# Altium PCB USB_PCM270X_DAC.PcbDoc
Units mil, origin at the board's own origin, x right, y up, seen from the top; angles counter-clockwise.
Board outline 1771 x 2186.5 mil, 2 copper layers (TopLayer, BottomLayer); 75 components, 58 nets, 240 pads, 54 vias.
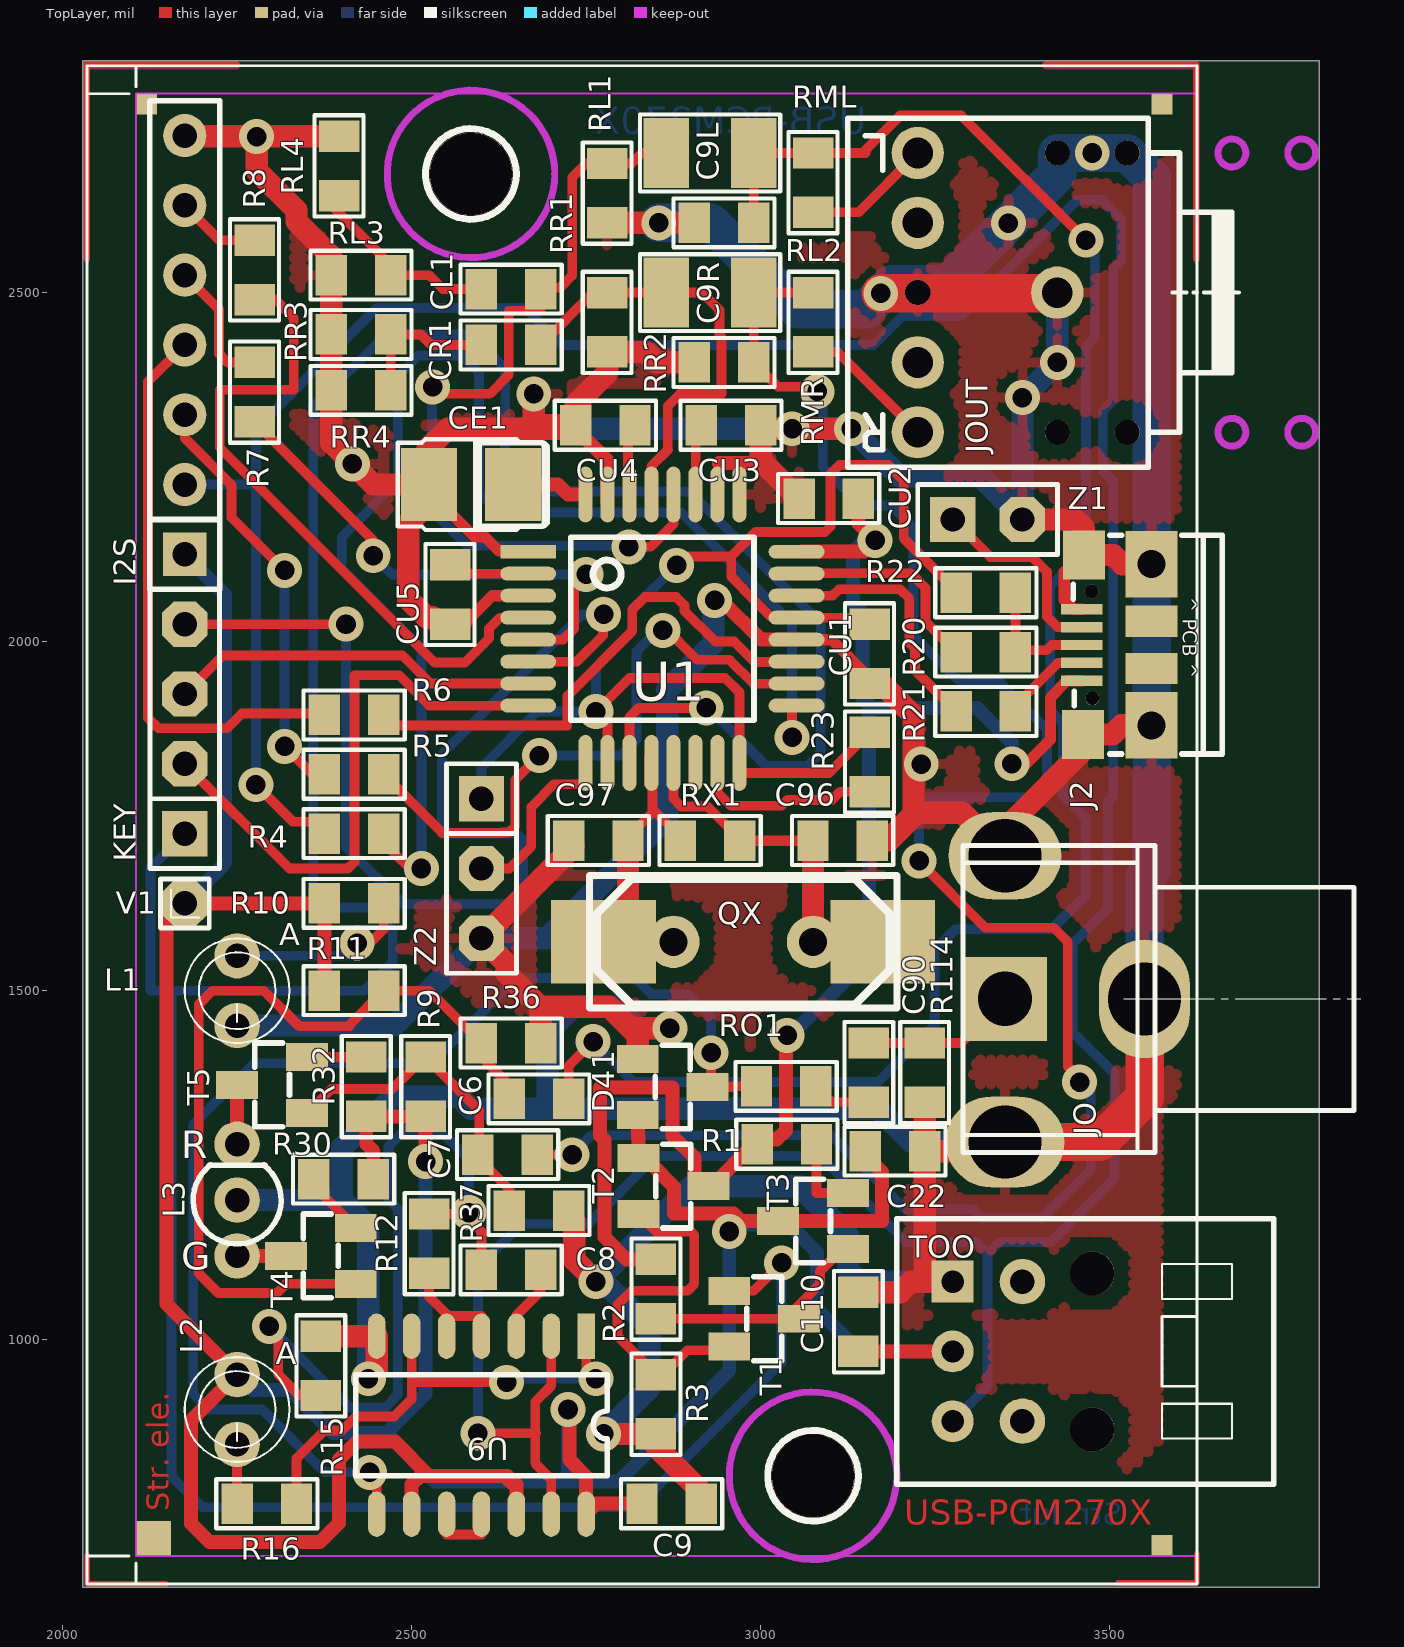
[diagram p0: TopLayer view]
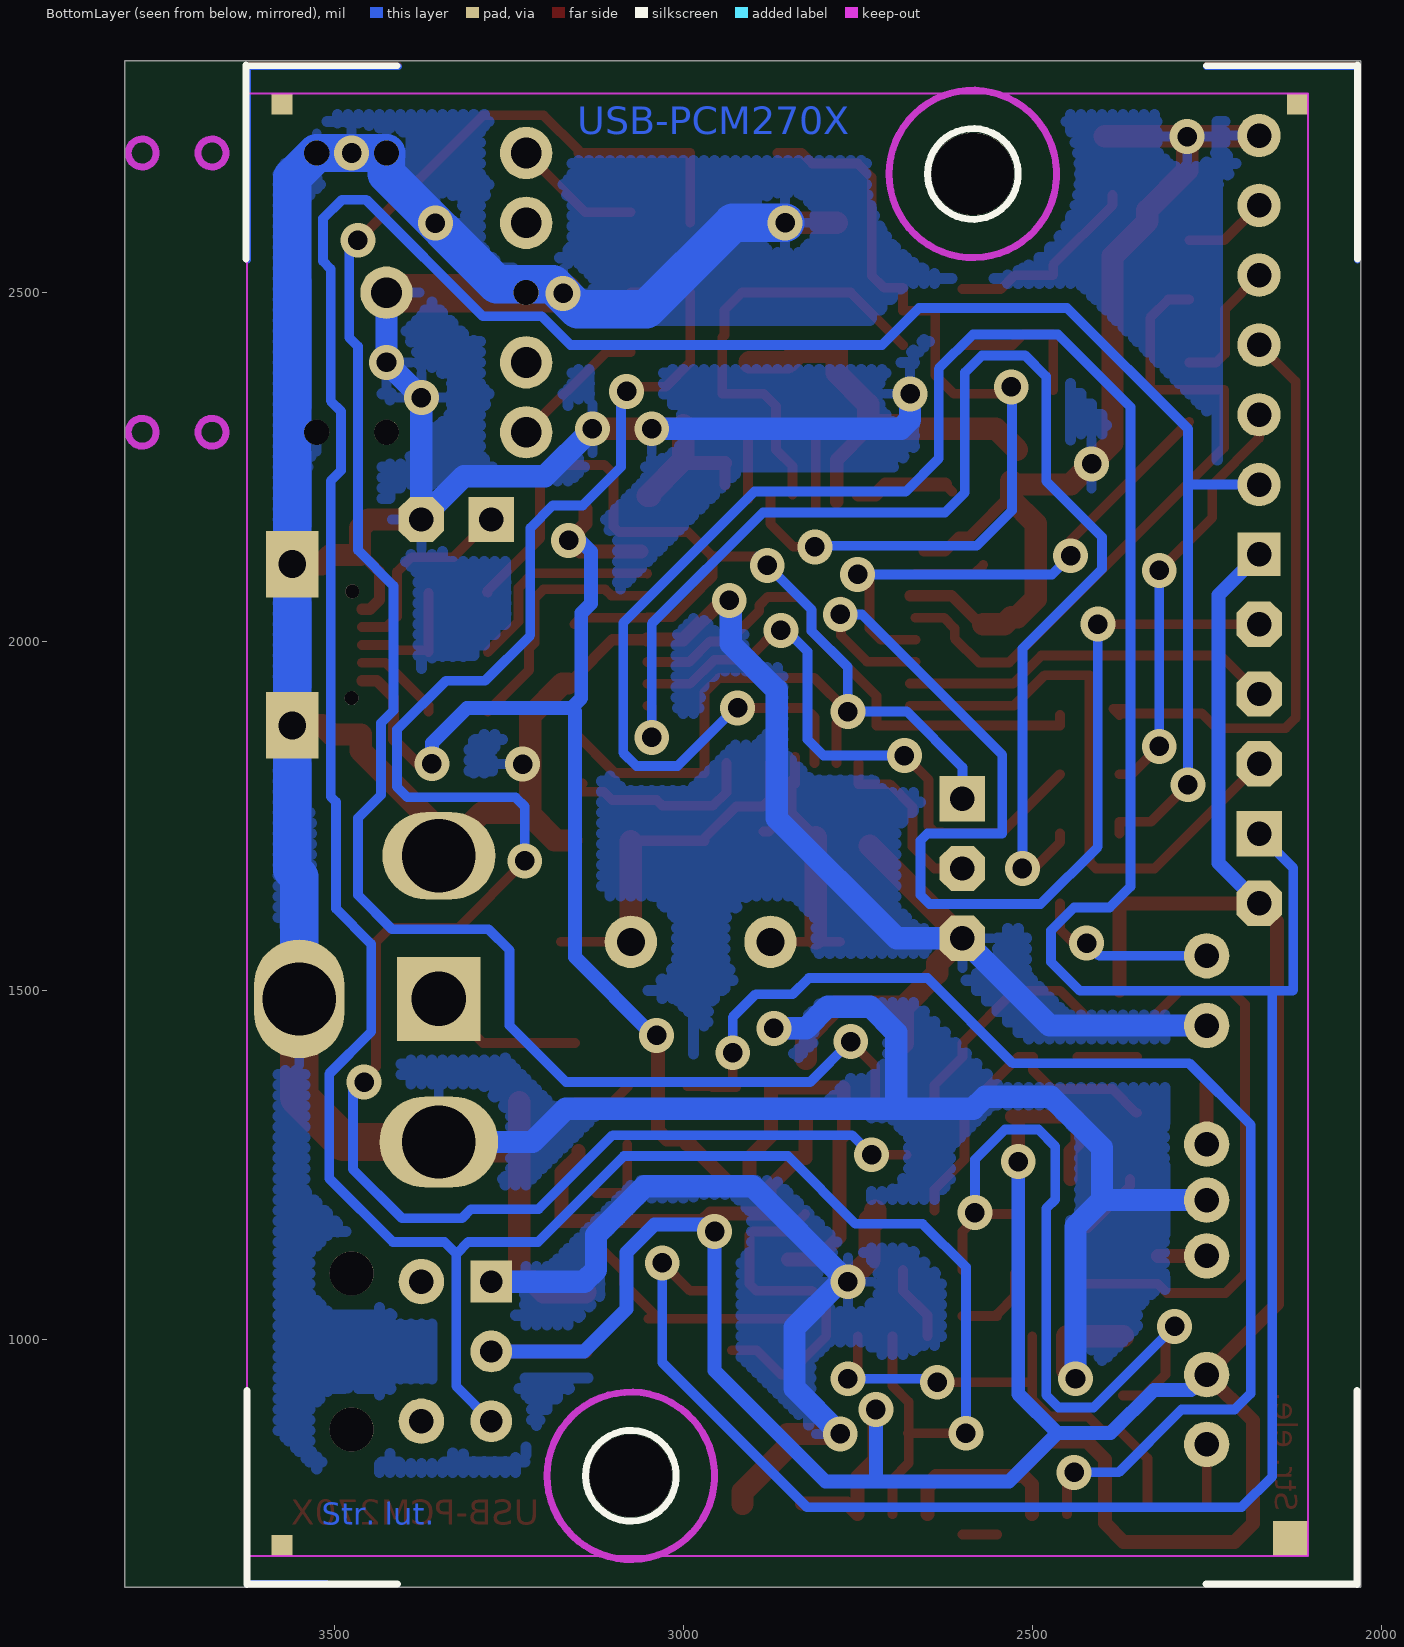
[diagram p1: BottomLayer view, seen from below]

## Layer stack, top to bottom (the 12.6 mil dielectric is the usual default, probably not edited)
TopLayer: signal copper 1.4
Dielectric: dielectric 12.6, FR-4, Dk 4.8
BottomLayer: signal copper 1.4

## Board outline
2029,645.5 3800,645.5 3800,2832 2029,2832

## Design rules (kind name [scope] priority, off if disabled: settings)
Clearance Clearance_2 [All] p1 off: gap=20
Clearance Clearance_1 [All] p2 off: gap=20
Clearance [All] p3: gap=9
ComponentClearance [All] p1: gap=-200 collisioncheckmode=3 verticalgap=10 showdistances=FALSE
FabricationTestPointUsage TestPointUsage [All] p1: valid=0 allowmultiple=FALSE
FabricationTestpoint Testpoint [All] p1: side=3 testpointundercomponent=TRUE minsize=40 maxsize=100 preferedsize=60 minholesize=20 maxholesize=40 preferedholesize=32 testpointgrid=1 allowsidetop=TRUE allowsidebottom=TRUE usegrid=TRUE gridtolerance=0.01
PlaneClearance [All] p1: clearance=10
PlaneConnect [All] p1: planeconnectstyle=Relief reliefexpansion=14 reliefentries=4 reliefconductorwidth=16 reliefairgap=10
PolygonConnect [All] p1: connectstyle=Relief reliefconductorwidth=14 reliefentries=4 polygonreliefangle="90 Angle"
RoutingCorners [All] p1: cornerstyle=45-Degree minsetback=10 maxsetback=200
RoutingPriority [All] p1: routingpriority=2
RoutingVias RoutingVias_B [InNetClass('BOLD3')] p1: holewidth=35 width=65 viastyle="Through Hole" minholewidth=28 minwidth=50 maxholewidth=63 maxwidth=100
RoutingVias [All] p2: holewidth=28 width=50 viastyle="Through Hole" minholewidth=28 minwidth=50 maxholewidth=63 maxwidth=100
SilkscreenOverComponentPads [All] p1: minsilkscreentomaskgap=10
SolderMaskExpansion [All] p1: expansion=2
Width Width_B [InNetClass('BOLD')] p1: maxlimit=100 minlimit=14 preferedwidth=32
Width Width_S [InNetClass('Srednie')] p2: maxlimit=100 minlimit=14 preferedwidth=20
Width [All] p3: maxlimit=100 minlimit=12 preferedwidth=14
20 further rules are at their usual default settings.

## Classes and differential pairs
net class Srednie: VBUS VCC
net class BOLD: GND

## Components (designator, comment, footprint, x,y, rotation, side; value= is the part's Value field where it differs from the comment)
C6 "1u0" 0805_C 2725,1345 r180 top
C7 "1u0" 0805_C 2680,1265 r180 top
C8 "100n" 0805_C 2685,1100 r180 top
C9 "100n" 0805_C 2830,765 r0 top
C9L "47uFc" 1210_C 2865,2700 r0 top
C9R "47uFc" 1210_C 2865,2500 r0 top
C22 "470n" 0805_C 3150,1270 r0 top
C90 "100n" 0805_C 3155,1340 r90 top
C96 "12p" 0805_C 3160,1715 r180 top
C97 "12p" 0805_C 2725,1715 r0 top
C110 "100n" 0805_C 3140,983.19 r90 top
CE1 "10uF" 3528_B 2635,2225 r180 top
CL1 "22n" 0805_C 2600,2505 r0 top
CR1 "22n" 0805_C 2600,2425 r0 top
CU1 "4u7" 0805_C 3156,1940 r90 top
CU2 "1u0" 0805_C 3055,2205 r0 top
CU3 "1u0" 0805_C 2915,2310 r0 top
CU4 "1u0" 0805_C 2735,2310 r0 top
CU5 "1u0" 0805_C 2555,2025 r90 top
D41 "BAT54S" SOT-23B_3D 2924,1362 r90 top
I2S "[7]" SIP7 2175,2125 r90 top
J2 "MICRO_USB_FV" MICRO_USB_FV_2 3460,1944 r180 top
JO "SPDIFOUT" CHINCH1_3D 3550,1488.19 r270 top
JOUT "JACK_OUT" JACK_NC+_3D 3425,2500 r180 top
KEY "[4]" SIP4 2175,1725 r90 top
L1 "LEDCZ" LED 2250,1550 r270 top
L2 "LEDBlue" LED 2250,950 r270 top
L3 "LED2C" LEDBD3 2250,1200 r270 top
QX "12MHz" XTAL5_3D 3075,1570 r180 top
R1 "10R" 0805_R 2995,1280 r0 top
R2 "1k5" 0805_R 2850,1115 r270 top
R3 "1k5" 0805_R 2850,865 r90 top
R4 "33R" 0805_R 2375,1725 r0 top
R5 "33R" 0805_R 2375,1810 r0 top
R6 "33R" 0805_R 2375,1895 r0 top
R7 "33R" 0805_R 2275,2400 r270 top
R8 "180R" 0805_R 2275,2575 r270 top
R9 "6k8" 0805_R 2520,1405 r270 top
R10 "470R" 0805_R 2375,1625 r0 top
R11 "6k8" 0805_R 2460,1500 r180 top
R12 "10k" 0805_R 2525,1095 r90 top
R15 "10k" 0805_R 2370,1005 r270 top
R16 "470R" 0805_R 2335,765 r180 top
R20 "22R" 0805_R 3365,1985 r180 top
R21 "22R" 0805_R 3365,1900 r180 top
R22 "1k5" 0805_R 3280,2070 r0 top
R23 "1k5" 0805_R 3156,1785 r90 top
R30 "200R" 0805_R 2360,1230 r0 top
R32 "330R" 0805_R 2435,1405 r270 top
R36 "39k" 0805_R 2685,1425 r180 top
R37 "39k" 0805_R 2725,1185 r180 top
R114 "200R" 0805_R 3235,1425 r270 top
RL1 "3k3" 0805_R 2780,2600 r90 top
RL2 "3k3" 0805_R 2905,2600 r0 top
RL3 "33R" 0805_R 2385,2525 r0 top
RL4 "33R" 0805_R 2396,2724 r270 top
RML "56R" 0805_R 3075,2615 r90 top
RMR "56R" 0805_R 3075,2415 r90 top
RO1 "120R" 0805_R 2994,1363 r0 top
RR1 "3k3" 0805_R 2780,2415 r90 top
RR2 "3k3" 0805_R 2905,2400 r0 top
RR3 "33R" 0805_R 2385,2440 r0 top
RR4 "33R" 0805_R 2385,2360 r0 top
RX1 "1M0" 0805_R 2970,1715 r180 top
T1 "BC847" SOT-23X_3D 3055,1030 r90 top
T2 "BC847" SOT-23X_3D 2925,1220 r90 top
T3 "BC857" SOT-23X_3D 3025,1170 r270 top
T4 "BC857" SOT-23X_3D 2320,1120 r270 top
T5 "BC857" SOT-23X_3D 2250,1365 r270 top
TOO "TOTX147PL" TOTX147_3D 3275,1083.19 r90 top
U1 "PCM2706" TQFP32_3D 2667,2128.79 r0 top
U9 "74LV00" SMD14_3D 2750,980 r270 top
V1 "Vcc" VIA 2175,1625 r0 top
Z1 "z" SIP2 3275,2175 r0 top
Z2 "FS" SIP3 2600,1775 r270 top

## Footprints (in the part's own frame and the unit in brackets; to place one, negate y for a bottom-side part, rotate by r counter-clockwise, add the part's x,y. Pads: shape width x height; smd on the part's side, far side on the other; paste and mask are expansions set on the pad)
0805_C [mil]
  rect 45x58 smd paste-2: 1(0,0) 2(85,0)
  silkscreen extent -30,-35 115,35
0805_R [mil]
  rect 45x58 smd paste-2: 1(0,0) 2(85,0)
  silkscreen extent -30,-35 115,35
1210_C [mil]
  rect 65x100 smd: 1(0,0) 2(125,0)
  silkscreen extent -38,-55 163,55
3528_B [mil]
  rect 80x105 smd paste-5: 1(-10,0) 2(110,0)
  silkscreen extent -60,-65 155,65
CHINCH1_3D [mil]
  rect 120x120 hole 78: 1(0,-200)
  oval 170x130 hole 105: 2(0,0)
  oval 125x162 hole 105: 3(-205,-200)
  oval 130x170 hole 105: 4(205,-200)
  silkscreen extent -220,-260 220,310
JACK_NC+_3D [mil]
  round 75 hole 44: 1(200,200) 2(200,-200) 3(0,0) 4(200,100) 5(200,-100)
  round 36 hole 36 unplated: 101(-100,200) 102(0,200) 103(200,0) 104(0,-200) 105(-100,-200)
  silkscreen extent -260,-250 300,250
LED [mil]
  round 65 hole 35: A(0,0) K(100,0)
  silkscreen extent -25,-75 125,75
LEDBD3 [mil]
  round 65 hole 35: 1(-80,0) 2(0,0) 3(80,0)
  silkscreen extent -50,-63 63,63
MICRO_USB_FV_2 [mil]
  rect 59x15 smd: 1(0,0) 2(0,-25.59) 3(0,-51.18) 4(0,-76.77) 5(0,-102.36)
  rect 75x95 hole 40: 10(-100,64) 11(-100,-167)
  rect 60x70 smd: 100(-2,77) 101(-3,-180)
  rect 75x45 smd: 101(-100,-17.5) 102(-100,-85)
  round 20 hole 20 unplated: 110(-15,25) 111(-14,-128)
  silkscreen extent -202,-209 12,105
SIP2 [mil]
  rect 65x65 hole 35: 1(0,0)
  oct 65x65 hole 35: 2(100,0)
  silkscreen extent -50,-50 150,50
SIP3 [mil]
  rect 65x65 hole 35: 1(0,0)
  oct 65x65 hole 35: 2(100,0) 3(200,0)
  silkscreen extent -50,-50 250,50
SIP4 [mil]
  rect 65x65 hole 35: 1(0,0)
  oct 65x65 hole 35: 2(100,0) 3(200,0) 4(300,0)
  silkscreen extent -50,-50 350,50
SIP7 [mil]
  rect 62x62 hole 35: 1(0,0)
  round 62 hole 35: 2(100,0) 3(200,0) 4(300,0) 5(400,0) 6(500,0) 7(600,0)
  silkscreen extent -50,-50 650,50
SMD14_3D [mil]
  rect 65x25 smd: 1(-25,0)
  oval 65x25 smd: 2(-25,-50) 3(-25,-100) 4(-25,-150) 5(-25,-200) 6(-25,-250) 7(-25,-300) 8(230,-300) 9(230,-250) 10(230,-200) 11(230,-150) 12(230,-100) 13(230,-50) 14(230,0)
  silkscreen extent 30,-330 175,30
SOT-23B_3D [mil]
  rect 40x60 smd paste-2: 1(40,100) 2(-40,100) 3(0,0)
  silkscreen extent -60,25 60,75
SOT-23X_3D [mil]
  rect 40x60 smd paste-2: B(40,100) C(0,0) E(-40,100)
  silkscreen extent -60,25 60,75
TOTX147_3D [mil]
  rect 60x60 hole 32: 1(0,0)
  round 60 hole 32: 2(-100,0) 3(-200,0)
  round 65 hole 35: 4(0,-100) 5(-200,-100)
  round 63 hole 63: 6(11.81,-200) 7(-211.81,-200)
  silkscreen extent -290,-460 90,80
TQFP32_3D [mil]
  rect 80x20 smd: 1(0,0)
  oval 80x20 smd: 2(0,-31.5) 3(0,-63) 4(0,-94.5) 5(0,-126) 6(0,-157.5) 7(0,-189) 8(0,-220.5) 17(384.5,-220.5) 18(384.5,-189) 19(384.5,-157.5) 20(384.5,-126) 21(384.5,-94.5) 22(384.5,-63) 23(384.5,-31.5) 24(384.5,0)
  oval 20x80 smd: 9(82,-302.5) 10(113.5,-302.5) 11(145,-302.5) 12(176.5,-302.5) 13(208,-302.5) 14(239.5,-302.5) 15(271,-302.5) 16(302.5,-302.5) 25(302.5,82) 26(271,82) 27(239.5,82) 28(208,82) 29(176.5,82) 30(145,82) 31(113.5,82) 32(82,82)
  silkscreen extent 61,-242 324,21
VIA [mil]
  oct 65x65 hole 35: 1(0,0)
  silkscreen extent -35,-35 35,35
XTAL5_3D [mil]
  round 75 hole 40: 1(0,0) 2(200,0)
  rect 150x120 smd: 3(-100,0) 4(300,0)
  silkscreen extent -120,-95 320,95

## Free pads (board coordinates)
  round 118 hole 118 unplated paste-5: 2(2585,2670) 2(3075,805)
  rect 30x30 all layers, no hole: 101(2120,2770) 101(3575,705) 101(3575,2770)
  rect 50x50 all layers, no hole: 102(2130,715)

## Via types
v1: diameter 50, hole 28, TopLayer to BottomLayer, tented both sides, 54 vias

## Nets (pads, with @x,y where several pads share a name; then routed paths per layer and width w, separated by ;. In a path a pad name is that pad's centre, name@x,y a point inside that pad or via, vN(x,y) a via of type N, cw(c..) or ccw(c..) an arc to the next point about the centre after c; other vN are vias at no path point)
BCLK: I2S.4 R6.1 | length 866.1
  TopLayer w14: I2S.4 2122.5,2372.5 2122.5,1890.5 2137,1876 2236,1876 2257,1897 2377,1897 2384,1904 2366,1904 R6.1
DIN: I2S.6 R8.1 | length 120.7
  TopLayer w14: I2S.6 2225,2575 R8.1
GND: C9.2 C22.2 C96.1 C97.1 C110.2 CE1.2 CU1.1 CU2.1 CU3.2 CU4.1 CU5.1 D41.1 I2S.7 J2.5 J2.10 J2.11 J2.100 J2.101@3463,2124 JO.2 JO.3 JO.4 JOUT.3 JOUT.101 JOUT.103 JOUT.104 JOUT.105 L1.K L3.2 R3.1 R15.1 R36.1 R37.1 R114.2 RL1.1 RL2.1 RL3.1 RL4.1 RR1.1 RR2.1 RR3.1 RR4.1 TOO.1 U1.1 U1.3 U1.20 U1.25 U1.26 U1.31 U9.7 Z1.2 Z2.3 | length 13405.8
  TopLayer w16: CE1.2@2525,2215 2590,2150 2605,2150 2625,2130 U1.1@2655,2130 ; CU5.1@2580,2030 2615.79,2065.79 U1.3@2675,2065.79 ; U1.26@2940,2224.79 2940,2256 ; U1.20 3101.21,2002.79 3156,1948 CU1.1 ; J2.101@3450,2115 3435,2100 3435,2060 3448.64,2046.36 J2.5
  TopLayer w20: CU4.1 2735,2305 2780,2260 U1.31@2780,2200.5 ; v1@2932,2057 2946,2057 3000.21,2002.79 U1.20 ; 2940,2256 2994.5,2256 3000,2261.5
  TopLayer w32: I2S.7 2176,2724 v1@2278,2724 ; R15.1 U9.7 2450,956 v1(2438,944) ; RL4.1 v1@2278,2724 ; CE1.2@2522,2275 2552,2305 CU4.1@2735,2305 ; CU5.1@2570,2025 2540,2025 2530,2035 2521,2035 2495,2061 2495,2169 2530,2204 2530,2230 CE1.2 2445,2225 2385,2285 RR4.1 RR3.1 RL3.1 2385,2552 2335,2602 2335,2618 2278,2675 v1@2278,2724 ; v1(2675,2355) 2675,2318 2683,2310 CU4.1 2735,2340 2780,2385 RR1.1 2835,2415 2850,2400 RR2.1 ; R37.1 R37.1@2725,1179 ; C97.1@2732.5,1707.5 Z2.3 2636,1539 2636,1525 2685,1476 R36.1 2685,1477 2783,1477 2824,1436 D41.1 2824,1446 v1(2870,1446) ; v1(2764,1083) 2733,1114 R37.1@2733,1171 ; v1(2775,865) R3.1 2850,847 2915,782 C9.2 ; RL1.1 v1(2854,2600) RL2.1 ; 3000,2260 3051.21,2208.79 CU2.1@3047,2208.79 ; 3000,2261.5 CU3.2@3000,2305 ; CU3.2 CU3.2@3000,2305 ; v1(3045,2305) CU3.2@3000,2305 ; v1@3051,2305 v1(3130,2305) ; C110.2 3200,1068.19 3215,1083.19 TOO.1 3235,1083.19 C22.2 ; CU1.1@3165,1940 3172.86,1940 3219,1893.86 3219,1750 3184,1715 C96.1 3181.86,1715 3221.86,1755 3288.19,1755 JO.3 3388.19,1693.19 3364,1717.38 3364,1746 3462,1844 J2.100 3504,1867 3517,1880 J2.10 ; R114.2 C22.2 ; JO.4 3298.19,1283.19 3285,1270 C22.2 ; Z1.2 3450.5,2175 3463,2162.5 3463,2124 3505,2124 3518,2111 J2.11 ; R37.1@2725,1179 2725,1171 R37.1@2733,1171 ; R37.1@2725,1179 R37.1@2733,1171
  TopLayer w55: v1(3172,2499) 3424,2499 JOUT.3 ; JO.4 3486.19,1283.19 3550,1347 JO.2@3550,1483.19
  BottomLayer w32: L3.2 2400,1200 ; L1.K 2475,1450 Z2.3 2694,1575 2866,1747 2866,1931 2932,1997 2932,2057 v1(2934,2059) ; v1(2438,944) 2438,1162 2400,1200 ; v1(2675,2355) 2675,2318 2688,2305 v1(3045,2305) ; 2696,1331 2695,1332 2695,1440 2732,1477 2793,1477 2824,1446 v1(2870,1446) ; v1(2775,865) 2840.5,930.5 2840.5,1017.5 2775,1083 v1(2764,1083) 2901,1220 3055,1220 3125,1150 3125,1100.11 3141.92,1083.19 TOO.1 ; v1(3130,2305) 3198,2237 3314,2237 Z1.2@3371,2180 ; JO.4 3215.81,1283.19 3168,1331 2584.57,1331 2567.57,1348 2473,1348 2400,1275 2400,1200 ; Z1.2 3375,2350 v1(3425,2400) JOUT.3 ; JO.2@3550,1483.19 JO.2
  BottomLayer w55: v1(2854,2600) 2928.75,2600 3052.75,2476 3151,2476 3187,2512 3267,2512 3425,2670 JOUT.104 JOUT.105 3560,2665 J2.11 J2.10 3560,1673.34 3550,1663.34 JO.2
  other v1: 3230,1824.56 2415,2254.56 3375,2349.56 3355,2599.56 3475,2700 2278,2723.56
LRCLK: I2S.5 R7.1 | length 189
  TopLayer w14: I2S.5 2224,2476 2224,2412.5 2236.5,2400 R7.1
MCLK: I2S.3 R5.1 | length 607.8
  TopLayer w14: I2S.3 2175,2291.47 2242,2224.47 2242,2178 v1(2318,2102) ; v1(2318,1850) 2358,1810 R5.1
  BottomLayer w14: v1(2318,1850) v1(2318,2102)
NetC6_2: C6.2 R11.1 R36.2 T4.B | length 1211.3
  TopLayer w14: T4.B 2320,1080 2307,1067 2223,1067 2195,1095 2195,1480 2215,1500 2288,1500 2339,1449 2411,1449 2411,1451 R11.1 2525,1500 R36.2 2600,1405 2640,1365 C6.2
NetC7_2: C7.2 R9.1 R37.2 T5.B | length 484
  TopLayer w14: T5.B 2351,1325 2385,1359 2472,1359 2499,1386 2499,1405 R9.1 2597,1328 2597,1258 2640,1215 R37.2
NetC8_1: C8.1 U9.3 | length 109.5
  TopLayer w14: U9.3 2650,1035 2685,1070 C8.1
NetC8_2: C8.2 R12.2 R15.2 | length 1115.4
  TopLayer w14: v1(2296,1019) 2309,1006 2309,950 2339,920 R15.2 ; R12.2 v1@2575,1180 ; v1(2582,1182) v1@2575,1180 ; C8.2 2600,1155 v1@2575,1180
  BottomLayer w14: v1(2296,1019) 2412,903 2462.5,903 2480,920.5 2480,1188 2467,1201 2467,1277 2491,1301 2539,1301 2582,1258 v1(2582,1182)
NetC9L_1: C9L.1 CL1.2 RL1.2 U1.28 | length 1232.8
  TopLayer w14: v1(2530,2365) 2530,2356 2529,2355 2612,2355 2639,2382 2639,2474 2685,2474 CL1.2 2685,2507 2712.5,2507 2730,2524.5 2730,2665 2750,2685 RL1.2 2815,2685 2830,2700 C9L.1 ; v1(2811.21,2135.79) 2842,2135.79 2875,2168.79 U1.28
  BottomLayer w14: v1(2530,2365) 2529,2364 2529,2188 2579.79,2137.21 v1@2799,2137.21
NetC9R_1: C9R.1 CR1.2 RR1.2 U1.29 | length 639.3
  TopLayer w14: CR1.2 2760,2500 RR1.2 C9R.1 2916,2500 2941,2475 2941,2439 2944,2436 2944,2355 2884.5,2355 2867,2337.5 2867,2275 ; U1.29 2843.5,2251.29 2867.11,2274.89
NetC90_1: C90.1 RO1.2 | length 85.5
  TopLayer w14: RO1.2 3102,1340 C90.1
NetC96_2: C96.2 QX.1 QX.3 RX1.1 U1.13 | length 629.3
  TopLayer w14: U1.13 2875,1775 2886,1764 2924,1764 2970,1718 RX1.1 ; QX.1 QX.3 ; C96.2@3075,1714 2969,1714 RX1.1 ; C96.2 RX1.1
  TopLayer w32: QX.1 C96.2@3075,1714
NetC97_2: C97.2 QX.2 QX.4 RX1.2 U1.12 | length 506.9
  TopLayer w14: QX.4 QX.2 2815,1570 QX.4@2810,1575 ; C97.2@2810,1720 2845,1755 2845,1801 2840,1796 U1.12@2840,1835 ; 2845,1760 2877,1728 RX1.2@2885,1728
  TopLayer w32: QX.4@2810,1575 C97.2@2810,1720
NetCE1_1: CE1.1 U1.32 | length 144
  TopLayer w14: CE1.1@2615,2215 CE1.1@2625,2225
  TopLayer w20: CE1.1@2625,2225 2710,2225 2724.21,2210.79 U1.32
NetCL1_1: CL1.1 RL3.2 RL4.2 | length 288.5
  TopLayer w14: RL4.2@2385,2640 2385,2625 2470,2540 RL3.2 2525,2525 2545,2505 CL1.1
NetCR1_1: CR1.1 RR3.2 RR4.2 | length 216.2
  TopLayer w14: RR4.2 RR3.2 2513.06,2440 2528.06,2425 CR1.1
NetCU3_1: CU3.1 U1.27 | length 119.2
  TopLayer w14: U1.27 2906.5,2219.34 2907,2218.84 U1.27@2907,2226.4 ; U1.27@2907,2204.01 CU3.1@2907,2306.4
NetCU4_2: CU4.2 U1.30 | length 118
  TopLayer w14: U1.30@2810,2192 CU4.2@2810,2310
NetCU5_2: CU5.2 U1.2 | length 102.3
  TopLayer w14: CU5.2@2570,2110 2582.71,2097.29 U1.2
NetD41_3: D41.3 RO1.1 U9.8 | length 1777.4
  TopLayer w14: v1(2440,810) 2450,810 U9.8 ; D41.3 D41.3@2929,1362 ; v1(2929,1411) D41.3@2929,1362 ; RO1.1 2959,1363 2958,1362 D41.3@2929,1362
  BottomLayer w14: v1(2440,810) 2376,810 2286,900 2210,900 2187,923 2187,1308 2275,1396 2528,1396 2650,1518 2820,1518 2843,1495 2896,1495 2929,1462 v1(2929,1411)
NetJ2_4: J2.4 Z1.1 | length 286.5
  TopLayer w14: Z1.1 3329,2121 3389,2121 3410,2100 3410,2035.77 3425,2020.77 J2.4
NetKEY_1: KEY.1 T1.B U1.11 | length 4978.3
  TopLayer w14: U1.11 2812,1891.79 2825.21,1905 v1(2922,1905) ; T1.B 2990,1070 v1(3030,1110)
  BottomLayer w14: 2156,1500 2156,804 2200,760 2823,760 3030,967 v1(3030,1110) ; KEY.1 2126,1676 2126,1500.76 2126.76,1500 2432,1500 2473,1541 2473,1586 2440,1619 2389,1619 2359,1649 2359,2336 2463,2440 2585,2440 2634,2391 2634,2262 2681,2215 2898,2215 3086,2027 3086,1840.79 3067,1821.79 3008,1821.79 2924.39,1905.39 v1@2925,1906
NetKEY_2: KEY.2 U1.8 | length 851.7
  TopLayer w14: KEY.2 2325,1675 2408.5,1675 2418,1684.5 2418,1952 2482,1952 2525.71,1908.29 U1.8@2675,1908.29
NetKEY_3: KEY.3 U1.7 | length 539.4
  TopLayer w14: KEY.3 2230,1980 2487,1980 2527,1940 U1.7@2675,1940
NetKEY_4: KEY.4 U1.6 | length 1668.5
  TopLayer w14: KEY.4 v1(2406,2025) ; U1.6 2736.5,1971.29 2774,2008.79 2774,2057.79 2775,2056.79 v1(2775,2039)
  BottomLayer w14: v1(2406,2025) 2406,1706 2488,1624 2647,1624 2660,1637 2660,1715 2650,1725 2543,1725 2543,1838 2744,2039 v1@2782,2039
NetL1_A: L1.A R10.2 | length 263
  TopLayer w14: v1(2422,1568) 2440.5,1568 2460,1587.5 R10.2
  BottomLayer w14: L1.A 2404,1550 v1(2422,1568)
NetL2_K: L2.K R16.2 | length 85
  TopLayer w14: R16.2 L2.K
NetL3_1: L3.1 T5.C | length 85
  TopLayer w20: L3.1 T5.C
NetL3_3: L3.3 T4.C | length 70
  TopLayer w20: L3.3 T4.C
NetR1_2: R1.2 T3.E | length 115
  TopLayer w14: R1.2 3080,1210 T3.E
NetR2_2: R2.2 T1.C T3.B | length 337.4
  TopLayer w14: R2.2@2844,1030 T1.C@3050,1030 ; T1.C@3042.5,1037.5 3085,1080 3085,1098 3117,1130 T3.B
NetR3_2: R3.2 T1.E T2.E | length 502.1
  TopLayer w14: T2.E 2850,1155 2900,1155 2905,1150 2905,1080 2895,1070 2815,1070 2795,1050 2795,1005 R3.2 2860,950 2895,985 T1.E@2930,985
NetR4_2: R4.2 U1.17 | length 1943
  TopLayer w14: R4.2 2460,1712.5 2514,1658.5 v1(2514,1675) ; v1(3045,1862.79) 3045,1908.29 U1.17
  BottomLayer w14: v1(2514,1675) 2514,1990 2400,2104 2400,2150 2480,2230 2480,2380 2510,2410 2572,2410 2596.5,2385.5 2596.5,2213.5 2625,2185 2885.74,2185 3045,2025.74 v1(3045,1862.79)
NetR5_2: R5.2 U1.18 | length 910.3
  TopLayer w14: R5.2 2544,1726 2628.47,1726 2628.97,1726.5 2639.13,1726.5 2648.5,1735.87 2648.5,1802.29 v1(2683,1836.79) ; v1(2860,2016) 2860,2022.79 2908.79,1974 2955.53,1974 2989.74,1939.79 U1.18
  BottomLayer w14: v1(2683,1836.79) 2799,1836.79 2822,1859.79 2822,1985.79 2859.5,2023.29 2860,2022.79 v1(2860,2016)
NetR6_2: R6.2 U1.19 | length 767.1
  TopLayer w14: R6.2 2460,1880 2723,1880 ; 2723,1881.79 2723,1922.29 2816,2015.29 2816,2045.79 2834.21,2064 2879,2064 2891,2052 2891,2044.02 2935.02,2000 2962.05,2000 2991.26,1970.79 3051,1970.79 U1.19
NetR7_2: R7.2 U1.5 | length 758.7
  TopLayer w14: R7.2 2445,2145 v1(2445,2123) ; U1.5 2717,2002.79 2733,2018.79 2733,2098.8 2750,2098.8 v1(2750,2096.21)
  BottomLayer w14: v1(2445,2123) 2471.79,2096.21 v1@2758,2096.21
NetR8_2: R8.2 U1.4 | length 963.2
  TopLayer w14: R8.2 2305,2490 2331,2464 2331,2361 2225,2361 2225,2278 2533,1970 2576.21,1970 2611,2004.79 2611,2018.79 2626.5,2034.29 U1.4
NetR12_1: R12.1 U9.4 U9.5 | length 121.4
  TopLayer w14: R12.1 2525,1062 2550,1037 2550,1034 U9.4@2600,1034
NetR16_1: R16.1 U9.1 U9.6 | length 688.1
  TopLayer w14: R16.1 2335,830 2375,870 2400,870 2420,890 2475,890 2500,915 2500,939 ; U9.6 2500,939 ; v1(2636,939) 2500,939 ; U9.1 2750,958 v1(2764,944)
  BottomLayer w14: v1(2636,939) 2641,944 v1(2764,944)
NetR23_1: R23.1 U1.15 | length 293.1
  TopLayer w14: U1.15 2938,1784 2957,1765 3030,1765 3038,1773 3102,1773 3114,1785 R23.1 R23.1@3144.21,1796.79
NetR30_1: R30.1 T4.E | length 94.9
  TopLayer w14: R30.1 2360,1220 T4.E
NetR32_1: R32.1 T5.E | length 85
  TopLayer w14: T5.E R32.1
NetU1_9: U1.9 Z2.2 | length 262.8
  TopLayer w14: Z2.2 2640,1675 2671.5,1706.5 2671.5,1763.29 2704,1795.79 2749,1795.79 U1.9
NetU9_10: U9.10 U9.11 | length 50
  TopLayer w14: U9.10@2550,721 U9.11@2600,721
SOUT: C90.2 JO.1 R114.1 | length 221.2
  TopLayer w14: C90.2 R114.1 3286.81,1425 JO.1
SPDIF_DO: I2S.2 R4.1 TOO.3 U9.2 U9.13 | length 5556.8
  TopLayer w14: v1(2277,1795) 2330,1742 2375,1742 R4.1 ; v1(2595,866) 2678,866 ; U9.13 2700,800 2677,823 2677,911 2700,934 U9.2
  BottomLayer w14: I2S.2 2275,2225 2277,2223 ; v1(2277,1795) 2277,2305 2450,2478 2662.25,2478 2715.25,2425 3161.52,2425 3202.52,2466 3287,2466 3454,2633 3489,2633 3516,2606 3516,2545 3505,2534 3505,2345 3490,2330 3490,2245 3505,2230 3505,1778 3497.5,1770.5 3497.5,1617.5 3447,1567 3447,1441 3507,1381 3507,1231 3416,1140 3342,1140 3325,1123 ; v1(2595,866) 2595,1104 2657,1166 2753,1166 2850,1263 3085,1263 3208,1140 3308,1140 3325,1123 ; TOO.3 3325,933.19 3325,1123
USBDN: J2.2 R21.1 | length 128.9
  TopLayer w14: R21.1 3365,1908.63 3425.96,1969.59 J2.2
USBDP: J2.3 R20.1 R22.2 | length 183.1
  TopLayer w14: R20.1 R20.1@3365,1987.7 ; R22.2 R20.1@3365,1987.7 ; J2.3 3417.18,1995.18 3409.7,1987.7 R20.1@3365,1987.7
USBXN: R21.2 U1.22 | length 360.5
  TopLayer w14: U1.22 3102.79,2065.79 3112,2075 3200,2075 3213,2062 3213,1998 3221,1990 3221,1959 R21.2
USBXP: R20.2 U1.23 | length 303.7
  TopLayer w14: U1.23 3052.21,2098 3215,2098 3236,2077 3236,2029 R20.2
VBUS: CU2.2 J2.1 R1.1 R2.1 T2.C U1.24 | length 2288
  TopLayer w16: v1(3360,1825) 3370,1815 3415,1860 3415,1920 3439,1944 J2.1
  TopLayer w20: R2.1 2808,1115 2776,1147 2776,1286.23 2770,1292.23 2770,1361 2874,1361 2874,1292 2905,1261 2905,1220 T2.C 2930,1220 2990,1280 2990,1282 R1.1@2995,1287 ; R1.1 R1.1@2995,1287 ; v1(3038,1436) 3036,1434 3036,1300 3023,1287 R1.1@2995,1287 ; U1.24@3059.5,2129 3148,2129 v1(3164,2145) 3148,2145 3156,2153 3140,2169 CU2.2@3140,2190
  BottomLayer w20: v1@3043,1436 3155,1548 3155,1900 3160.12,1905.12 3146,1919.23 3146,2040.77 3132,2054.77 3132,2129 3148,2145 v1(3164,2145) ; 3160,1905 3310,1905 3360,1855 v1(3360,1825)
VCC: C9.1 C22.1 C110.1 D41.2 I2S.1 L2.A R9.2 R10.1 R11.2 R30.2 R32.2 T2.B T3.C TOO.2 U9.9 U9.12 U9.14 V1.1 | length 5812.9
  TopLayer w20: R11.2 R10.1 V1.1 2149,1599 2149,1051 L2.A 2184,884 2184,737 2210.5,710.5 2369,710.5 2396,737.5 2396,828.23 2421.77,854 2476,854 2525,805 ; R30.2 2445,1270 2435,1280 R32.2 R9.2 ; U9.9 2500,792.5 2512.5,805 2525,805 ; v1(2520,1255) R9.2 ; R9.2@2529,1320 R9.2 ; U9.12 2650,788 ; v1(2724,900) 2726,898 2726,828 2750,804 U9.14 2765,765 C9.1 ; D41.2 2824,1291 2825,1290 T2.B 2845,1260 2845,1250 2876,1219 2876,1181 2961,1181 2972,1170 T3.C 3174,1170 3174,1240 3150,1264 C22.1 ; C110.1 TOO.2 ; 2525,805 2633,805 ; 2633,805 2650,788 ; 2633,805 2637.5,805 2650,792.5 2650,788
  BottomLayer w20: V1.1 2233,1683 2233,2067 I2S.1 ; L2.A 2272.26,927.74 2325.76,927.74 2387.5,866 2464,866 ; v1(2520,1255) 2520,922 2464,866 ; v1(2724,900) 2724,798 2725,797 ; TOO.2 3141.81,983.19 3081,1044 3081,1125 3041,1165 2970,1165 2960,1155 v1(2955,1155) 2955,956 2796,797 2725,797 ; 2464,866 2533,797 2725,797
VDD: CU1.2 R22.1 R23.2 U1.10 U1.16 U1.21 Z2.1 | length 2027.1
  TopLayer w14: U1.10 2780.5,1883.29 v1(2764,1899.79) 2812.21,1948 2949,1948 2969.5,1927.5 U1.16 2969.5,1812 3098,1812 R23.2 ; v1@2892,2121.79 2957.79,2121.79 2993,2157 3092,2157 3100,2165 3100,2240 3113,2253 3183,2253 3205,2231 3205,2148 3281.5,2071.5 R22.1 ; 2958,2122 2958,2092.98 2975,2075.98 2975,2075.52 3015.73,2034.79 3051,2034.79 U1.21 3146.71,2034.29 CU1.2
  BottomLayer w14: Z2.1 2600,1820 2680.39,1900.39 ; 2679.79,1899.79 v1(2764,1899.79) ; v1@2764.21,1900 2764.21,1963.5 2816,2015.29 2816,2045.79 v1(2879.5,2109.29) v1@2892,2121.79
VOL: C6.1 C9L.2 RL2.2 RML.2 | length 2666.3
  TopLayer w14: C6.1 2725,1392 v1(2760,1427) ; RL2.2 C9L.2 RML.2 3150,2700 3150,2704 3200,2754 3287,2754 v1(3466,2575)
  BottomLayer w14: v1(2760,1427) 2818,1369 3168,1369 3249,1450 3249,1558 3279,1588 3417,1588 3466,1637 3466,1747.47 3433,1780.47 3433,1883.53 3415,1901.53 3415,2080 3466,2131 3466,2423 3478.5,2435.5 3478.5,2562.5 v1(3466,2575)
VOR: C7.1 C9R.2 RMR.2 RR2.2 | length 2822.2
  TopLayer w14: C7.1 v1(2730,1265) ; RMR.2 C9R.2 RR2.2 3025,2365 3075,2365 3081.06,2358.94 v1(3081.06,2358.5) ; v1@3226.5,1685.5 3322,1590 3420,1590 3440,1570 3440,1391 3457,1374 v1(3457,1369)
  BottomLayer w14: v1(2730,1265) 2758,1293 3101,1293 3207,1187 3304,1187 3317,1174 3403,1174 3473,1244 3473,1358 3457,1374 v1(3457,1369) ; v1(3081.06,2358.5) v1@3089,2350.56 ; v1@3090,2349.56 v1@3089,2350.56 ; v1(3227,1686) 3227,1764 3240,1777 3395,1777 3410,1792 3410,1874 3340,1944 3284,1944 3219,2009 3219,2163 3187,2195 3144,2195 3089,2250 v1@3089,2350.56
VOYL: JOUT.2 RML.1 | length 185.2
  TopLayer w14: RML.1 3140,2615 JOUT.2
VOYR: JOUT.1 RMR.1 | length 197.6
  TopLayer w14: RMR.1 3110,2415 JOUT.1
pads on no net: J2.101@3560,1961.5 J2.102 J2.110 J2.111 JOUT.4 JOUT.5 JOUT.102 TOO.4 TOO.5 TOO.6 TOO.7 U1.14
copper on no net: | length 2896
  TopLayer w8: 2035,650 2148,650 2035,650 ; 2035,650 2035,691 2035,650 ; 3625,652 3512,652 3625,652 ; 3625,652 3625,693 3625,652
  TopLayer w10: 2034,2549 2034,2827 ; 2035,2826 2250,2826 ; 3408,2826 3623,2826 ; 3624,2549 3624,2827
  BottomLayer w8: 2034.5,690.5 2034.5,649.5 2147.5,649.5 ; 3511.5,651.5 3624.5,651.5 3624.5,692.5
  BottomLayer w10: 2034,2547 2034,2825 ; 2035,2824 2250,2824 ; 3408,2824 3623,2824 ; 3624,2547 3624,2825

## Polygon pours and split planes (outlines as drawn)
GND on TopLayer "TopLayer-GND" (hatched 90Degree grid 15 track 16, remove dead copper, pour order 1000): 2411,1449 2475,1385 2875,1385 3100,1385 3115,1400 3120,1405 3300,1405 3305,1400 3305,1275 3225,1275 3210,1260 3210,1205 3210,850 3245,815 3530,815 3570,855 3570,1330 3585,1345 3600,1360 3600,1380 3600,2680 3535,2745 2755,2745 2725,2715 2720,2710 2720,2540 2410,2540 2350,2600 2345,2595 2325,2595 2325,1535 2411,1449
GND on BottomLayer "BottomLayer-GND" (hatched 90Degree grid 15 track 16, remove dead copper, pour order 1001): 2145,2755 3500,2755 3570,2685 3580,2675 3580,2670 3580,870 3520,810 2365,810 2310,865 2310,1570 2235,1645 2235,2640 2200,2675 2145,2675

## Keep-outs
KeepOutLayer:
  circle w10: c3775,2300 r20
  circle w10: c3675,2700 r20
  circle w10: c3775,2700 r20
  circle w10: c2585,2670 r120
  circle w10: c3075,805 r120
  circle w10: c3675,2300 r20
  lines w3: 2105,690 3625,690 3625,2785 2105,2785 2105,690

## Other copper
TopLayer:
  text "Str. ele." at 2152,754 h32 r90
  text "USB-PCM270X" at 3206,735 h36
BottomLayer:
  text "USB-PCM270X" at 3152,2727 h40
  text "Str. lut." at 3518,735 h32

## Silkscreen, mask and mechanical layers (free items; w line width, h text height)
TopOverlay:
  circle w10: c2585,2670 r65
  circle w10: c3075,805 r65
  lines w4: 2035,690 2095,690 ; 2035,2785 2095,2785 ; 2105,650 2105,680 ; 2105,2795 2105,2825 ; 2035,650 3625,650 3625,1560 3625,2825 2035,2825 2035,650
  text "A" at 2310,1565 h32
  text "R" at 2170,1260 h40
  text "G" at 2170,1100 h40
  text "A" at 2305,965 h32
BottomOverlay:
  circle w10: c2585,2670 r65
  circle w10: c2585,2670 r65
  circle w10: c3075,805 r65
  circle w10: c3075,805 r65
  lines w10: 2034,2548 2034,2826 ; 2035,927 2035,649 2036,650 2251,650 ; 2035,2825 2250,2825 ; 3409,650 3624,650 ; 3410,2825 3625,2825 ; 3625,649 3625,927 ; 3626,2548 3626,2826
